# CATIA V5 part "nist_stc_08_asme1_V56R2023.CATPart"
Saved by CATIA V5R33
Part number: NIST PMI STC 08 ASME1
Revision: C
Description: NIST PMI test model downloaded from http://go.usa.gov/mGVm
Bounding box of the stored display mesh (mm): x -155.797 to 155.797, y -111.347 to 111.347, z 0 to 48.26
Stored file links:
  C:\Users\rla3\OneDrive - NIST\STEP\NIST Test Models\CAx Test Rounds Data\R53J\NIST Files\nist_stc_08_asme1_V56R2023.CATPart
  C:\Program Files\Dassault Systemes\B32\win_b64\resources\graphic\CATTPSGeneralTolerance.xlsx
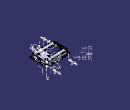
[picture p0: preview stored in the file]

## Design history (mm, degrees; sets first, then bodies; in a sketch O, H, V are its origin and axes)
TTRSSet1
f4a2d38f3ddc11d3a929006094b99c4b_11 "CATTPSSet"
AxisSystem1: origin (69.85, -20.955, 48.26), X (-1, 0, 0), Y (0, -1, 0), Z (0, 0, 1)
Set1 "MBD_A_GEOM"
  Plane1: type Equation, A 0.57735, B -0.57735, C -0.57735, Length -28.26, RefPoint vertex [face of Fillet7 | start face of Pad1 | face of Pad1 from Sketch6.L4], RefAxis AxisSystem10
  Sketch1 on face of Pad2 from Sketch7.L3, origin (0, -102.4573, 0), H (1, 0, 0), V (0, 0, 1)
    circle A1 centre (92.6766, 27.0377) radius 12.7126
    circle A2 centre (91.4412, 27.0377) radius 11.8782
    radius A1 = 12.7126
    radius A2 = 11.8782
Set2
  Point1: type Center, Curve edge [face of Hole1 | start face of Pad1]
  Point2: type OnPlane, Support end face of Pad2, H 142.875, V 98.425, Direction (1, 0, 0)
  Point3: type Center, Curve edge [end face of Pad2 | face of Hole5]
Set3 "MBD_A"
  AxisSystem2 "ABC": origin (142.875, 98.425, 0), X (0, -1, 0), Y (-1, 0, 0), Z (0, 0, -1)
  AxisSystem3 "DBC": origin (142.875, 98.425, 48.26), X (0, 1, 0), Y (-1, 0, 0), Z (0, 0, 1)
Set4 "MBD_B"
  AxisSystem4: origin (142.875, 98.425, 0), X (0, -1, 0), Y (-1, 0, 0), Z (0, 0, -1)
  AxisSystem5: origin (142.875, 98.425, 48.26), X (0, 1, 0), Y (-1, 0, 0), Z (0, 0, 1)
  Sketch2 on face of Pad2 from Sketch7.L3, origin (0, -102.4573, 0), H (1, 0, 0), V (0, 0, 1)
    axis line L1 (0, -16.144) -> (0, 81.9836)
    point P5 (0, -16.144)
    line L2 (50.8, 45.212) -> (50.8, 11.684)
    line L3 (-50.8, 45.212) -> (-50.8, 11.684)
    projected line E4 (121.8957, 11.684) -> (-121.8957, 11.684) from edge [face of Pad2 from Sketch7.L3 | face of Fillet9]
    projected line E5 (50.8, 11.684) -> (-50.8, 11.684) from edge [face of Pad2 from Sketch7.L3 | face of Fillet9]
    distance L1 L2 = 50.8
    distance L1 L3 = 50.8
    coincidence: P5 V
    vertical: L1 V, L2 V, L3 V
  AxisSystem6 "DE-F": origin (-38.1, 0, 48.26), X (0, 1, 0), Y (-1, 0, 0), Z (0, 0, 1)
  Sketch3 on end face of Pad2, origin (0, 0, 48.26), H (1, 0, 0), V (0, 1, 0)
    axis line L1 (-38.1, 55.626) -> (-38.1, -55.626)
    point P1 (-38.1, -55.626)
    point P2 (-38.1, 55.626)
    reference projected point E3 (-38.1, -55.626) from axis of face of RectPattern3
    reference projected point E4 (-38.1, 55.626) from axis of face of RectPattern3
    point P3 (-38.1, 0)
    vertical: L1 V
    coincidence: E3 P1, E4 P2
    midpoint: P3 L1
  Fill1: Boundary Sketch2
Set5 "MBD_C"
  Sketch4 on end face of Pad2, origin (0, 0, 48.26), H (1, 0, 0), V (0, 1, 0)
    axis line L1 (109.22, -20.955) -> (109.22, -78.105)
    point P1 (109.22, -20.955)
    point P2 (109.22, -78.105)
    reference projected point E1 (109.22, -20.955) from axis of face of Hole4
    reference projected point E2 (109.22, -78.105) from axis of face of RectPattern4
    point P3 (109.22, -49.53)
    vertical: L1 V
    coincidence: E1 P1, E2 P2
    midpoint: P3 L1
  AxisSystem7 "DG": origin (109.22, -49.53, 48.26), X (0, 1, 0), Y (-1, 0, 0), Z (0, 0, 1)
  AxisSystem8: origin (142.875, 98.425, 48.26), X (0, 1, 0), Y (-1, 0, 0), Z (0, 0, 1)
Set6 "MBD_D"
  Sketch5 on end face of Pad2, origin (0, 0, 48.26), H (1, 0, 0), V (0, 1, 0)
    axis line L1 (69.85, -25.1263) -> (69.85, -67.31)
    point P2 (69.85, -67.31)
    reference projected point E1 (69.85, -67.31) from axis of face of RectPattern5
    point P3 (69.85, -46.2182)
    vertical: L1 V
    coincidence: E1 P2
    midpoint: P3 L1
  AxisSystem9 "DHJ": origin (69.85, -46.2182, 48.26), X (0, 1, 0), Y (-1, 0, 0), Z (0, 0, 1)
  AxisSystem10 "DKL": origin (69.85, 25.4, 48.26), X (0, 1, 0), Y (-1, 0, 0), Z (0, 0, 1)
  AxisSystem11: origin (142.875, 98.425, 48.26), X (0, 1, 0), Y (-1, 0, 0), Z (0, 0, 1)
Body1 (main body)
  Sketch6 on xy-plane, origin (0, 0, 0), H (1, 0, 0), V (0, 1, 0)
    line L1 (-155.7973, 111.3473) -> (155.7973, 111.3473)
    line L2 (155.7973, 111.3473) -> (155.7973, -111.3473)
    line L3 (155.7973, -111.3473) -> (-155.7973, -111.3473)
    line L4 (-155.7973, -111.3473) -> (-155.7973, 111.3473)
    length L3 = 311.5945
    distance V L4 = 155.7973
    length L2 = 222.6945
    distance H L1 = 111.3473
    horizontal: L1 H, L3 H
    vertical: L2 V, L4 V
  Pad1: profile Sketch6, direction (0, 0, 1), length 10.16
  Sketch7 on end face of Pad1, origin (0, 0, 10.16), H (1, 0, 0), V (0, 1, 0)
    line L1 (-123.1583, 102.4573) -> (123.1583, 102.4573)
    line L2 (146.0183, 79.5973) -> (146.0183, -79.5973)
    line L3 (123.1583, -102.4573) -> (-123.1583, -102.4573)
    line L4 (-146.0183, -79.5973) -> (-146.0183, 79.5973)
    line L5 (123.1583, 102.4573) -> (146.0183, 79.5973)
    line L6 (146.0183, -79.5973) -> (123.1583, -102.4573)
    line L7 (-123.1583, 102.4573) -> (-146.0183, 79.5973)
    point P1 (-142.7555, 82.86)
    line L8 (-146.0183, -79.5973) -> (-123.1583, -102.4573)
    point P2 (-123.1583, 102.4573)
    point P5 (-123.1583, -102.4573)
    point P6 (123.1583, -102.4573)
    point P9 (123.1583, 102.4573)
    reference projected line E1 (-155.7973, 111.3473) -> (-155.7973, -111.3473) from edge [face of Pad1 from Sketch6.L4 | end face of Pad1]
    reference projected line E2 (155.7973, -111.3473) -> (155.7973, 111.3473) from edge [face of Pad1 from Sketch6.L2 | end face of Pad1]
    reference projected line E3 (-155.7973, -111.3473) -> (155.7973, -111.3473) from edge [face of Pad1 from Sketch6.L3 | end face of Pad1]
    reference projected line E4 (155.7973, 111.3473) -> (-155.7973, 111.3473) from edge [face of Pad1 from Sketch6.L1 | end face of Pad1]
    angle L1 L7 = 45
    distance L4 E1 = 9.779
    distance L2 E2 = 9.779
    distance L3 E3 = 8.89
    distance E4 L1 = 8.89
    distance L4 P2 = 22.86
    distance P9 L2 = 22.86
    angle L5 L1 = 45
    distance L2 P6 = 22.86
    angle L3 L6 = 45
    distance P5 L4 = 22.86
    angle L3 L8 = 45
    horizontal: L1 H, L3 H
    vertical: L2 V, L4 V
    coincidence: P1 L7
  Pad2: profile Sketch7, direction (0, 0, 1), length 38.1
  Sketch8 on end face of Pad1, origin (138.8883, 98.2031, 10.16), H (1, 0, 0), V (0, 1, 0)
    point P1 (3.9867, 0.2219)
    reference intersected line E1 through (0, -98.2031) direction (-1, 0) from zx-plane
    reference intersected line E2 through (-138.8883, 0) direction (0, 1) from yz-plane
    distance E1 P1 = 98.425
    distance E2 P1 = 142.875
  Hole1: placed by Sketch8, at (142.875, 98.425, 10.16) direction (0, 0, -1), diameter 6.0325, through (limit type 6)
  RectPattern1: of Hole1, direction 1 instances 2, spacing 285.75, along edge [face of Pad1 from Sketch6.L1 | end face of Pad1], direction 2 instances 2, spacing 196.85, along edge [face of Pad1 from Sketch6.L2 | end face of Pad1] reversed
  Sketch9 on start face of Pad1, origin (0, 0, 0), H (1, 0, 0), V (0, -1, 0)
    line L1 (120.528, 96.1073) -> (139.6683, 76.967)
    line L2 (139.6683, 76.967) -> (139.6683, -76.967)
    line L3 (139.6683, -76.967) -> (120.528, -96.1073)
    line L4 (120.528, -96.1073) -> (-120.528, -96.1073)
    line L5 (-120.528, -96.1073) -> (-139.6683, -76.967)
    line L6 (-139.6683, -76.967) -> (-139.6683, 76.967)
    line L7 (-139.6683, 76.967) -> (-120.528, 96.1073)
    line L8 (-120.528, 96.1073) -> (120.528, 96.1073)
  Pocket1: profile Sketch9, direction (0, 0, 1), length 44.831
  Sketch10 on end face of Pad2, origin (0, 0, 48.26), H (1, 0, 0), V (0, 1, 0)
    point P1 (-107.95, 57.15)
    line L1 (-107.95, 57.15) -> (-90.17, 57.15)
    line L2 (31.75, 57.15) -> (31.75, 33.02)
    line L3 (31.75, -57.15) -> (13.97, -57.15)
    line L4 (-107.95, -57.15) -> (-107.95, -33.02)
    point P3 (31.75, -57.15)
    point P4 (-107.95, -57.15)
    reference intersected line E1 through (0, 0) direction (0, 1) from yz-plane
    reference intersected line E2 through (0, 0) direction (-1, 0) from zx-plane
    arc A1 centre (-106.426, 25.4) radius 7.62 from (-106.426, 17.78) to (-106.426, 33.02) ccw
    point P5 (-106.426, 25.4)
    reference intersected line E3 through (0, 0) direction (-1, 0) from zx-plane
    line L5 (-106.426, 33.02) -> (-107.95, 33.02)
    point P6 (-106.426, 33.02)
    line L6 (-106.426, 17.78) -> (-107.95, 17.78)
    point P7 (-106.426, 17.78)
    point P8 (-107.95, 33.02)
    line L7 (-107.95, 33.02) -> (-107.95, 57.15)
    point P9 (-107.95, 17.78)
    construction line L8 (0, 0) -> (-140, 0)
    point P11 (-107.95, -33.02)
    point P12 (-106.426, -33.02)
    line L9 (-106.426, -33.02) -> (-107.95, -33.02)
    point P13 (-106.426, -17.78)
    arc A2 centre (-106.426, -25.4) radius 7.62 from (-106.426, -17.78) to (-106.426, -33.02) cw
    point P15 (-107.95, -17.78)
    line L10 (-106.426, -17.78) -> (-107.95, -17.78)
    line L11 (-107.95, -17.78) -> (-107.95, 17.78)
    axis line L12 (-38.1, -57.15) -> (-38.1, 57.15)
    point P16 (-38.1, -57.15)
    point P17 (-38.1, 57.15)
    point P18 (30.226, 33.02)
    point P19 (30.226, 17.78)
    arc A3 centre (30.226, 25.4) radius 7.62 from (30.226, 17.78) to (30.226, 33.02) cw
    point P21 (31.75, 17.78)
    line L13 (30.226, 17.78) -> (31.75, 17.78)
    point P22 (31.75, 33.02)
    line L14 (30.226, 33.02) -> (31.75, 33.02)
    point P23 (31.75, -17.78)
    point P24 (30.226, -17.78)
    line L15 (30.226, -17.78) -> (31.75, -17.78)
    point P25 (30.226, -33.02)
    arc A4 centre (30.226, -25.4) radius 7.62 from (30.226, -17.78) to (30.226, -33.02) ccw
    point P27 (31.75, -33.02)
    line L16 (30.226, -33.02) -> (31.75, -33.02)
    line L17 (31.75, 17.78) -> (31.75, -17.78)
    line L18 (31.75, -33.02) -> (31.75, -57.15)
    arc A5 centre (6.35, -55.626) radius 7.62 from (13.97, -55.626) to (-1.27, -55.626) ccw
    point P28 (6.35, -55.626)
    line L19 (13.97, -55.626) -> (13.97, -57.15)
    point P29 (13.97, -55.626)
    line L20 (-1.27, -55.626) -> (-1.27, -57.15)
    point P30 (-1.27, -55.626)
    line L21 (-1.27, -57.15) -> (-30.48, -57.15)
    point P32 (-1.27, -57.15)
    point P33 (-74.93, -57.15)
    point P34 (-74.93, -55.626)
    line L22 (-74.93, -55.626) -> (-74.93, -57.15)
    point P35 (-90.17, -57.15)
    point P36 (-90.17, -55.626)
    line L23 (-90.17, -55.626) -> (-90.17, -57.15)
    arc A6 centre (-82.55, -55.626) radius 7.62 from (-90.17, -55.626) to (-74.93, -55.626) cw
    line L24 (-90.17, -57.15) -> (-107.95, -57.15)
    point P38 (-90.17, 57.15)
    point P39 (-90.17, 55.626)
    line L25 (-90.17, 55.626) -> (-90.17, 57.15)
    point P40 (-74.93, 55.626)
    arc A7 centre (-82.55, 55.626) radius 7.62 from (-90.17, 55.626) to (-74.93, 55.626) ccw
    point P42 (-74.93, 57.15)
    line L26 (-74.93, 55.626) -> (-74.93, 57.15)
    point P43 (-1.27, 57.15)
    point P44 (-1.27, 55.626)
    line L27 (-1.27, 55.626) -> (-1.27, 57.15)
    point P45 (13.97, 55.626)
    arc A8 centre (6.35, 55.626) radius 7.62 from (13.97, 55.626) to (-1.27, 55.626) cw
    line L28 (13.97, 55.626) -> (13.97, 57.15)
    line L29 (13.97, 57.15) -> (31.75, 57.15)
    line L30 (-74.93, 57.15) -> (-45.72, 57.15)
    arc A9 centre (-38.1, -55.626) radius 7.62 from (-30.48, -55.626) to (-45.72, -55.626) ccw
    point P48 (-38.1, -55.626)
    line L31 (-30.48, -55.626) -> (-30.48, -57.15)
    point P49 (-30.48, -55.626)
    line L32 (-45.72, -55.626) -> (-45.72, -57.15)
    point P50 (-45.72, -55.626)
    line L33 (-45.72, -57.15) -> (-74.93, -57.15)
    point P51 (-30.48, -57.15)
    point P52 (-45.72, -57.15)
    point P53 (-45.72, 57.15)
    point P54 (-45.72, 55.626)
    line L34 (-45.72, 55.626) -> (-45.72, 57.15)
    point P55 (-30.48, 55.626)
    arc A10 centre (-38.1, 55.626) radius 7.62 from (-30.48, 55.626) to (-45.72, 55.626) cw
    point P57 (-30.48, 57.15)
    line L35 (-30.48, 55.626) -> (-30.48, 57.15)
    line L36 (-30.48, 57.15) -> (-1.27, 57.15)
    distance L4 E1 = 107.95
    distance E2 L3 = 57.15
    distance P5 L4 = 1.524
    radius A1 = 7.62
    distance E3 P5 = 25.4
    distance P4 P1 = 114.3
    radius A5 = 7.62
    distance L3 P28 = 1.524
    distance P28 L12 = 44.45
    distance P3 P4 = 139.7
    radius A9 = 7.62
    distance L21 P48 = 1.524
    horizontal: L1 H, L3 H, L5 H, L6 H, L8 H, L21 H, L24 H, L29 H, L30 H, L33 H, L36 H
    vertical: L2 V, L4 V, L7 V, L11 V, L12 V, L17 V, L18 V, L20 V, L19 V, L31 V, L32 V
    tangency: L5 A1, L6 A1, L19 A5, L20 A5, L31 A9, L32 A9
    coincidence: L4 P8, L4 L11, L2 L17, L17 L18, L3 P16, L3 L21, L1 P17, L1 L29, P48 L12, L21 L33, L30 L36
    symmetry: P8 P11 L8, P6 P12 L8, L5 L9 L8, P7 P13 L8, A1 A2 L8, P9 P15 L8, L6 L10 L8, P6 P18 L12, P7 P19 L12, A1 A3 L12, P9 P21 L12, L6 L13 L12, P8 P22 L12, L5 L14 L12, P15 P23 L12, P13 P24 L12, L10 L15 L12, P12 P25 L12, A2 A4 L12, P11 P27 L12, L9 L16 L12, P32 P33 L12, P30 P34 L12, L20 L22 L12, P29 P36 L12, L19 L23 L12, A5 A6 L12, P35 P38 L8, P36 P39 L8, L23 L25 L8, P34 P40 L8, A6 A7 L8, P33 P42 L8, L22 L26 L8, P32 P43 L8, P30 P44 L8, L20 L27 L8, P29 P45 L8, A5 A8 L8, L19 L28 L8, P52 P53 L8, P50 P54 L8, L32 L34 L8, P49 P55 L8, A9 A10 L8, P51 P57 L8, L31 L35 L8
  Pocket2: profile Sketch10, direction (0, 0, -1), through (limit type 6)
  Sketch11 on end face of Pad2, origin (-103.9484, 24.3967, 48.26), H (1, 0, 0), V (0, 1, 0)
    point P1 (-2.4776, 1.0033)
    reference projected arc E1 centre (-2.4776, 1.0033) radius 7.62 from (-2.4776, -6.6167) to (-2.4776, 8.6233) ccw from edge [end face of Pad2 | face of Pocket2 from Sketch10.A1]
    concentricity: E1 P1
  Hole2: placed by Sketch11, at (-106.426, 25.4, 48.26) direction (0, 0, -1), diameter 5.4102, through (limit type 6)
  RectPattern2: of Hole2, direction 1 instances 2, spacing 50.8, along edge [end face of Pad2 | face of Pocket2 from Sketch10.L11], direction 2 instances 2, spacing 136.652, along edge [end face of Pad2 | face of Pocket2 from Sketch10.L21]
  Sketch12 on end face of Pad2, origin (-83.348, -53.7047, 48.26), H (1, 0, 0), V (0, 1, 0)
    point P1 (0.798, -1.9213)
    reference projected point E1 (0.798, -1.9213) from axis of face of Pocket2 from Sketch10.A6
    coincidence: E1 P1
  Hole3: placed by Sketch12, at (-82.55, -55.626, 48.26) direction (0, 0, -1), diameter 5.4102, through (limit type 6)
  RectPattern3: of Hole3, direction 1 instances 3, spacing 44.45, along edge [end face of Pad2 | face of Pocket2 from Sketch10.L33], direction 2 instances 2, spacing 111.252, along edge [end face of Pad2 | face of Pocket2 from Sketch10.L11] reversed
  Sketch13 on end face of Pad2, origin (0, 0, 48.26), H (1, 0, 0), V (0, 1, 0)
    line L1 (95.25, -35.56) -> (123.19, -35.56)
    line L2 (123.19, -35.56) -> (123.19, -63.5)
    line L3 (123.19, -63.5) -> (95.25, -63.5)
    line L4 (95.25, -63.5) -> (95.25, -35.56)
    reference intersected line E1 through (0, 0) direction (0, 1) from yz-plane
    reference intersected line E2 through (0, 0) direction (-1, 0) from zx-plane
    length L1 = 27.94
    length L2 = 27.94
    distance E1 L4 = 95.25
    distance E2 L1 = 35.56
    horizontal: L1 H, L3 H
    vertical: L2 V, L4 V
  Pocket3: profile Sketch13, direction (0, 0, -1), through (limit type 6)
  Sketch14 on end face of Pad2, origin (108.1397, -22.5136, 48.26), H (1, 0, 0), V (0, 1, 0)
    point P1 (1.0803, 1.5586)
    reference intersected line E1 through (-108.1397, 0) direction (0, 1) from yz-plane
    reference intersected line E2 through (0, 22.5136) direction (-1, 0) from zx-plane
    distance E1 P1 = 109.22
    distance E2 P1 = 20.955
  Hole4: placed by Sketch14, at (109.22, -20.955, 48.26) direction (0, 0, -1), diameter 6.35, through (limit type 6)
  RectPattern4: of Hole4, direction 1 instances 2, spacing 57.15, along edge [end face of Pad2 | face of Pocket3 from Sketch13.L2] reversed, direction 2 instances 2, spacing 111.252
  Sketch15 on end face of Pad2, origin (96.9796, 25.3434, 48.26), H (1, 0, 0), V (0, 1, 0)
    point P1 (-27.1296, 0.0566)
    reference intersected line E1 through (-96.9796, 0) direction (0, 1) from yz-plane
    reference intersected line E2 through (0, -25.3434) direction (-1, 0) from zx-plane
    distance E1 P1 = 69.85
    distance P1 E2 = 25.4
  Hole5: placed by Sketch15, at (69.85, 25.4, 48.26) direction (0, 0, -1), diameter 5.7912, through (limit type 6)
  RectPattern5: of Hole5, direction 1 instances 2, spacing 92.71, along edge [face of Pad2 from Sketch7.L2 | end face of Pad2] reversed, direction 2 instances 2, spacing 111.252
  Sketch16 on end face of Pad2, origin (70.1334, 59.5545, 48.26), H (1, 0, 0), V (0, 1, 0)
    point P1 (-0.2834, 7.7555)
    reference intersected line E1 through (0, -59.5545) direction (-1, 0) from zx-plane
    reference intersected line E2 through (-70.1334, 0) direction (0, 1) from yz-plane
    distance E1 P1 = 67.31
    distance E2 P1 = 69.85
  Hole6: placed by Sketch16, at (69.85, 67.31, 48.26) direction (0, 0, -1), diameter 6.1468, through (limit type 6)
  RectPattern6: of Hole6, direction 1 instances 2, spacing 92.71, along edge [face of Pad2 from Sketch7.L2 | end face of Pad2] reversed, direction 2 instances 2, spacing 111.252
  Sketch17 on end face of Pad2, origin (0, 0, 48.26), H (1, 0, 0), V (0, 1, 0)
    construction line L1 (50, 46.355) -> (180, 46.355)
    construction line L2 (59.69, 70) -> (59.69, -80)
    reference intersected line E1 through (0, 0) direction (0, 1) from yz-plane
    reference intersected line E2 through (0, 0) direction (-1, 0) from zx-plane
    arc A1 centre (59.69, 54.61) radius 7.62 from (67.31, 54.61) to (52.07, 54.61) ccw
    point P5 (59.69, 54.61)
    arc A2 centre (59.69, 38.1) radius 7.62 from (67.31, 38.1) to (52.07, 38.1) cw
    line L3 (46.99, 52.705) -> (46.99, 40.005)
    line L4 (46.99, 52.705) -> (52.07, 52.705)
    point P7 (46.99, 52.705)
    line L5 (52.07, 54.61) -> (52.07, 52.705)
    line L6 (67.31, 54.61) -> (67.31, 51.435)
    point P8 (67.31, 54.61)
    point P9 (67.31, 38.1)
    arc A3 centre (67.31, 46.355) radius 5.08 from (67.31, 41.275) to (67.31, 51.435) ccw
    point P10 (67.31, 46.355)
    line L7 (67.31, 41.275) -> (67.31, 38.1)
    point P12 (52.312, 52.705)
    point P13 (67.31, 54.61)
    line L8 (46.99, 40.005) -> (52.07, 40.005)
    line L9 (52.07, 38.1) -> (52.07, 40.005)
    axis line L10 (-21.2756, -46.355) -> (171.7584, -46.355)
    reference intersected line E3 through (0, 0) direction (-1, 0) from zx-plane
    arc A4 centre (59.69, -38.1) radius 7.62 from (67.31, -38.1) to (52.07, -38.1) ccw
    point P24 (59.69, -38.1)
    arc A5 centre (59.69, -54.61) radius 7.62 from (52.07, -54.61) to (67.31, -54.61) ccw
    point P25 (59.69, -54.61)
    point P26 (67.31, -54.61)
    arc A6 centre (67.31, -46.355) radius 5.08 from (67.31, -51.435) to (67.31, -41.275) ccw
    point P27 (67.31, -46.355)
    line L11 (67.31, -38.1) -> (67.31, -41.275)
    point P28 (67.31, -38.1)
    line L12 (67.31, -54.61) -> (67.31, -51.435)
    line L13 (52.07, -38.1) -> (52.07, -54.61)
    distance E1 L2 = 59.69
    distance E2 L1 = 46.355
    radius A1 = 7.62
    distance P5 L1 = 8.255
    distance L3 L2 = 12.7
    distance L1 L4 = 6.35
    radius A3 = 5.08
    distance E3 L10 = 46.355
    distance P24 P25 = 16.51
    distance L10 P24 = 8.255
    radius A6 = 5.08
    horizontal: L1 H, L4 H, L10 H
    vertical: L2 V, L3 V, L6 V, L7 V, L5 V, L9 V, L11 V
    coincidence: P5 L2, P7 L3, P8 A1, P9 A2, L6 P10, L6 L7, A1 P12, L6 P13, P12 L4, P24 L2, P25 L2, A5 P26, P26 L6, P27 L10, P28 A4, P27 L11
    symmetry: A1 A2 L1, L4 L8 L1
    tangency: L5 A1, L9 A2, L6 A1, A4 L6, A5 L6, L11 A4, L12 A5, L13 A5
    equidistance: P8 P9 P10
  Pocket4: profile Sketch17, direction (0, 0, -1), through (limit type 6)
  Sketch18 on end face of Pad2, origin (0, 0, 48.26), H (1, 0, 0), V (0, 1, 0)
    line L1 (-130.81, 79.375) -> (-118.11, 79.375)
    line L2 (-118.11, 79.375) -> (-118.11, -79.375)
    line L3 (-118.11, -79.375) -> (-130.81, -79.375)
    line L4 (-130.81, -79.375) -> (-130.81, 79.375)
    reference intersected line E1 through (0, 0) direction (-1, 0) from zx-plane
    reference intersected line E2 through (0, 0) direction (0, 1) from yz-plane
    length L1 = 12.7
    distance E1 L1 = 79.375
    length L4 = 158.75
    distance E2 L2 = 118.11
    horizontal: L1 H, L3 H
    vertical: L2 V, L4 V
  Pocket5: profile Sketch18, direction (0, 0, -1), length 1.27
  Fillet1: radius 3.175, on edge [face of Pocket2 from Sketch10.L24 | face of Pocket2 from Sketch10.L4]; edge [face of Pocket2 from Sketch10.L4 | face of Pocket2 from Sketch10.L9]; edge [face of Pocket2 from Sketch10.L10 | face of Pocket2 from Sketch10.L11]; edge [face of Pocket2 from Sketch10.L11 | face of Pocket2 from Sketch10.L6]; edge [face of Pocket2 from Sketch10.L5 | face of Pocket2 from Sketch10.L7]; edge [face of Pocket2 from Sketch10.L7 | face of Pocket2 from Sketch10.L1]; edge [face of Pocket2 from Sketch10.L1 | face of Pocket2 from Sketch10.L25]; edge [face of Pocket2 from Sketch10.L26 | face of Pocket2 from Sketch10.L30]; edge [face of Pocket2 from Sketch10.L30 | face of Pocket2 from Sketch10.L34]; edge [face of Pocket2 from Sketch10.L35 | face of Pocket2 from Sketch10.L36]; edge [face of Pocket2 from Sketch10.L36 | face of Pocket2 from Sketch10.L27]; edge [face of Pocket2 from Sketch10.L28 | face of Pocket2 from Sketch10.L29]; edge [face of Pocket2 from Sketch10.L29 | face of Pocket2 from Sketch10.L2]; edge [face of Pocket2 from Sketch10.L2 | face of Pocket2 from Sketch10.L14]; edge [face of Pocket2 from Sketch10.L13 | face of Pocket2 from Sketch10.L17]; edge [face of Pocket2 from Sketch10.L17 | face of Pocket2 from Sketch10.L15]; edge [face of Pocket2 from Sketch10.L16 | face of Pocket2 from Sketch10.L18]; edge [face of Pocket2 from Sketch10.L18 | face of Pocket2 from Sketch10.L3]; edge [face of Pocket2 from Sketch10.L3 | face of Pocket2 from Sketch10.L19]; edge [face of Pocket2 from Sketch10.L20 | face of Pocket2 from Sketch10.L21]; edge [face of Pocket2 from Sketch10.L21 | face of Pocket2 from Sketch10.L31]; edge [face of Pocket2 from Sketch10.L32 | face of Pocket2 from Sketch10.L33]; edge [face of Pocket2 from Sketch10.L33 | face of Pocket2 from Sketch10.L22]; edge [face of Pocket2 from Sketch10.L23 | face of Pocket2 from Sketch10.L24]
  Fillet2: radius 3.175, on edge [face of Pocket5 from Sketch18.L3 | face of Pocket5 from Sketch18.L4]; edge [face of Pocket5 from Sketch18.L2 | face of Pocket5 from Sketch18.L3]; edge [face of Pocket5 from Sketch18.L4 | face of Pocket5 from Sketch18.L1]; edge [face of Pocket5 from Sketch18.L1 | face of Pocket5 from Sketch18.L2]
  Fillet3: radius 0.762, on edge [face of Pocket5 from Sketch18.L4 | end face of Pocket5]
  Fillet4: radius 1.5875, on edge [face of Pocket4 from Sketch17.L8 | face of Pocket4 from Sketch17.L3]; edge [face of Pocket4 from Sketch17.L3 | face of Pocket4 from Sketch17.L4]
  Fillet5: radius 1.5875, on edge [face of Pocket3 from Sketch13.L3 | face of Pocket3 from Sketch13.L4]; edge [face of Pocket3 from Sketch13.L4 | face of Pocket3 from Sketch13.L1]; edge [face of Pocket3 from Sketch13.L1 | face of Pocket3 from Sketch13.L2]; edge [face of Pocket3 from Sketch13.L2 | face of Pocket3 from Sketch13.L3]
  Fillet6: radius 3.048, on edge [face of Pad2 from Sketch7.L4 | face of Pad2 from Sketch7.L7]; edge [face of Pad2 from Sketch7.L7 | end face of Pad2]; edge [face of Pad2 from Sketch7.L4 | end face of Pad2]; edge [face of Pad2 from Sketch7.L8 | face of Pad2 from Sketch7.L4]; edge [face of Pad2 from Sketch7.L8 | end face of Pad2]; edge [face of Pad2 from Sketch7.L3 | face of Pad2 from Sketch7.L8]; edge [face of Pad2 from Sketch7.L3 | end face of Pad2]; edge [face of Pad2 from Sketch7.L6 | face of Pad2 from Sketch7.L3]; edge [face of Pad2 from Sketch7.L6 | end face of Pad2]; edge [face of Pad2 from Sketch7.L2 | face of Pad2 from Sketch7.L6]; edge [face of Pad2 from Sketch7.L2 | end face of Pad2]; edge [face of Pad2 from Sketch7.L5 | face of Pad2 from Sketch7.L2]; edge [face of Pad2 from Sketch7.L5 | end face of Pad2]; edge [face of Pad2 from Sketch7.L1 | face of Pad2 from Sketch7.L5]; edge [face of Pad2 from Sketch7.L1 | end face of Pad2]; edge [face of Pad2 from Sketch7.L7 | face of Pad2 from Sketch7.L1]
  Fillet7: radius 3.048, on edge [face of Pad1 from Sketch6.L1 | face of Pad1 from Sketch6.L2]; edge [face of Pad1 from Sketch6.L1 | end face of Pad1]; edge [face of Pad1 from Sketch6.L2 | end face of Pad1]; edge [face of Pad1 from Sketch6.L4 | face of Pad1 from Sketch6.L1]; edge [face of Pad1 from Sketch6.L4 | end face of Pad1]; edge [face of Pad1 from Sketch6.L3 | face of Pad1 from Sketch6.L4]; edge [face of Pad1 from Sketch6.L3 | end face of Pad1]; edge [face of Pad1 from Sketch6.L2 | face of Pad1 from Sketch6.L3]
  Fillet8: radius 3.048, on edge [face of Pocket1 from Sketch9.L8 | face of Pocket1 from Sketch9.L1]; edge [face of Pocket1 from Sketch9.L8 | end face of Pocket1]; edge [face of Pocket1 from Sketch9.L1 | end face of Pocket1]; edge [face of Pocket1 from Sketch9.L7 | face of Pocket1 from Sketch9.L8]; edge [face of Pocket1 from Sketch9.L7 | end face of Pocket1]; edge [face of Pocket1 from Sketch9.L6 | face of Pocket1 from Sketch9.L7]; edge [face of Pocket1 from Sketch9.L6 | end face of Pocket1]; edge [face of Pocket1 from Sketch9.L5 | face of Pocket1 from Sketch9.L6]; edge [face of Pocket1 from Sketch9.L5 | end face of Pocket1]; edge [face of Pocket1 from Sketch9.L4 | face of Pocket1 from Sketch9.L5]; edge [face of Pocket1 from Sketch9.L4 | end face of Pocket1]; edge [face of Pocket1 from Sketch9.L3 | end face of Pocket1]; edge [face of Pocket1 from Sketch9.L3 | face of Pocket1 from Sketch9.L4]; edge [face of Pocket1 from Sketch9.L2 | end face of Pocket1]; edge [face of Pocket1 from Sketch9.L2 | face of Pocket1 from Sketch9.L3]; edge [face of Pocket1 from Sketch9.L1 | face of Pocket1 from Sketch9.L2]
  Sketch19 on end face of Pad2, origin (103.8066, 57.5041, 48.26), H (1, 0, 0), V (0, 1, 0)
    point P1 (7.9534, 5.9959)
    reference intersected line E1 through (0, -57.5041) direction (-1, 0) from zx-plane
    reference intersected line E2 through (-103.8066, 0) direction (0, 1) from yz-plane
    distance E1 P1 = 63.5
    distance E2 P1 = 111.76
  Hole7: placed by Sketch19, at (111.76, 63.5, 48.26) direction (0, 0, -1), diameter 30.5587, through (limit type 6)
  Sketch20 on end face of Pad2, origin (92.1729, 62.3356, 48.26), H (1, 0, 0), V (0, 1, 0)
    point P1 (5.2996, 1.1644)
    reference intersected line E1 through (0, -62.3356) direction (-1, 0) from zx-plane
    reference intersected line E2 through (-92.1729, 0) direction (0, 1) from yz-plane
    distance E1 P1 = 63.5
    distance E2 P1 = 97.4725
  Hole8: placed by Sketch20, at (97.4725, 63.5, 48.26) direction (0, 0, -1), diameter 6.35, through (limit type 6)
  Sketch21 on end face of Pad2, origin (0, 0, 48.26), H (1, 0, 0), V (0, 1, 0)
    axis line L1 (-38.1, 55.626) -> (-38.1, -55.626)
    point P1 (-38.1, -55.626)
    point P2 (-38.1, 55.626)
    reference projected point E3 (-38.1, -55.626) from axis of face of RectPattern3
    reference projected point E4 (-38.1, 55.626) from axis of face of RectPattern3
    point P3 (-38.1, 0)
    vertical: L1 V
    coincidence: E3 P1, E4 P2
    midpoint: P3 L1
  Fillet9: radius 1.524, on edge [end face of Pad1 | face of Pad2 from Sketch7.L3]
  Sketch22 "Main View" on face of Pad2 from Sketch7.L2, origin (146.0183, 0, 0), H (0, 1, 0), V (0, 0, 1)
    line L1 (-6.1589, 40.4) -> (-6.1589, 29.5957)
    arc A1 centre (-1.9632, 29.5957) radius 4.1957 from (-6.1589, 29.5957) to (-1.9632, 25.4) ccw
    line L2 (-1.9632, 25.4) -> (13.2373, 25.4)
    arc A2 centre (12.5189, 29.9115) radius 4.5683 from (13.2373, 25.4) to (13.2373, 34.4229) ccw
    line L3 (13.2373, 34.4229) -> (3.6106, 34.4229)
    arc A3 centre (3.6106, 35.8333) radius 1.4104 from (3.7255, 37.239) to (3.6106, 34.4229) ccw
    line L4 (3.7255, 37.239) -> (19.4156, 37.239)
    line L5 (19.4156, 37.239) -> (19.4156, 25.4)
    line L6 (19.4156, 25.4) -> (22.5181, 25.4)
    line L7 (22.5181, 25.4) -> (22.5181, 37.239)
    line L8 (22.5181, 37.239) -> (28.9274, 37.239)
    line L9 (28.9274, 37.239) -> (28.9274, 40.4)
    line L10 (28.9274, 40.4) -> (3.3241, 40.4)
    arc A4 centre (3.3241, 35.8533) radius 4.5467 from (3.3241, 40.4) to (3.6681, 31.3196) ccw
    line L11 (3.6681, 31.3196) -> (12.7199, 31.3196)
    arc A5 centre (12.5972, 29.9083) radius 1.4166 from (12.7774, 28.5032) to (12.7199, 31.3196) ccw
    line L12 (12.7774, 28.5032) -> (-1.9341, 28.5032)
    line L13 (-3.0266, 29.5957) -> (-3.0266, 40.4)
    line L14 (-3.0266, 40.4) -> (-6.1589, 40.4)
    line L15 (-27.94, 25.4) -> (-27.94, 37.5621)
    arc A6 centre (-24.679, 37.5621) radius 3.261 from (-22.2848, 39.7761) to (-27.94, 37.5621) ccw
    line L16 (-22.2848, 39.7761) -> (-12.02, 28.6757)
    arc A7 centre (-11.7155, 28.9572) radius 0.4146 from (-12.02, 28.6757) to (-11.3023, 28.9919) ccw
    line L17 (-11.3023, 28.9919) -> (-11.3023, 40.4)
    line L18 (-11.3023, 40.4) -> (-8.1701, 40.4)
    line L19 (-8.1701, 40.4) -> (-8.1701, 28.9171)
    line L20 (-14.4332, 26.7194) -> (-23.9003, 37.009)
    arc A8 centre (-24.2976, 36.6435) radius 0.5399 from (-23.9003, 37.009) to (-24.8375, 36.6435) ccw
    line L21 (-24.8375, 36.6435) -> (-24.8375, 25.4)
    line L22 (-24.8375, 25.4) -> (-27.94, 25.4)
    arc A9 centre (-1.9341, 29.5957) radius 1.0926 from (-3.0266, 29.5957) to (-1.9341, 28.5032) ccw
    arc A10 centre (-11.6872, 28.9171) radius 3.5171 from (-14.4332, 26.7194) to (-8.1701, 28.9171) ccw
  Pocket6: profile Sketch22, direction (-1, 0, 0), length 2.54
